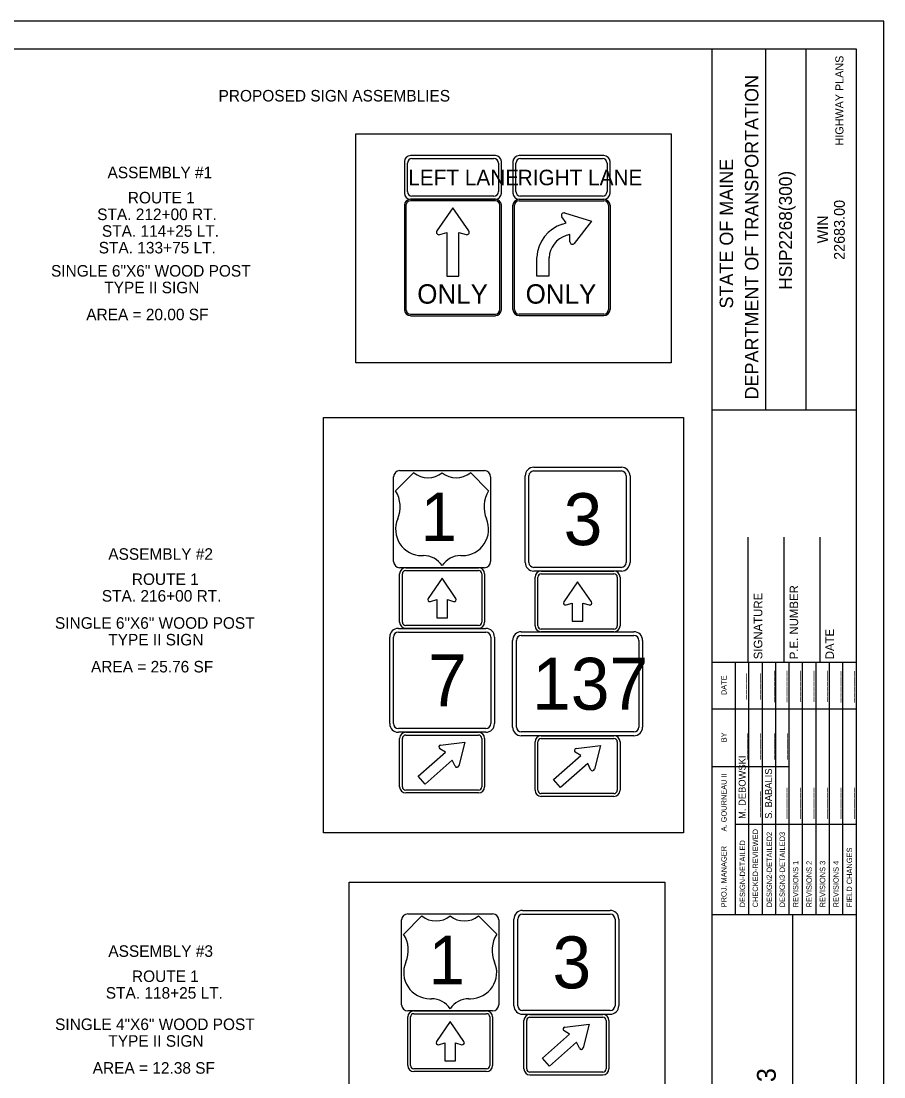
# Model space of a CAD drawing. Extents: x 29767 to 1670682, y 5748 to 339066.
# Drawn here: x 1670383.4 to 1670682.5, y 338699.8 to 339065.8 of the extents above; entities that cross this region are included whole.
import ezdxf

# ---------------------------------------------------------------- set-up
doc = ezdxf.new("R2010")
doc.units = 0
for name, color, linetype in [('D_Roadway_Pavement', 7, 'Continuous'), ('E_ROW_Line', 7, 'Continuous'), ('PDRAIN', 7, 'Continuous'), ('S_Curb_Type_5', 7, 'Continuous'), ('TEXT', 7, 'Continuous')]:
    doc.layers.add(name, color=color, linetype=linetype)

msp = doc.modelspace()

# ---------------------------------------------------------------- linework, layer by layer
at = {"layer": 'D_Roadway_Pavement'}
msp.add_lwpolyline([(1669832.5, 338515.81), (1670682.5, 338515.81), (1670682.5, 339065.81), (1669832.5, 339065.81)], close=True, dxfattribs=at)
at = {"layer": 'PDRAIN'}
for p, q in [((1670547.83, 339019.21), (1670518.39, 339019.21)), ((1670518.92, 339018.15), (1670547.31, 339018.15)), ((1670585.47, 339019.21), (1670556.04, 339019.21)), ((1670556.56, 339018.15), (1670584.95, 339018.15)), ((1670516.29, 339017.1), (1670516.29, 339006.17)), ((1670517.34, 339006.69), (1670517.34, 339016.58)), ((1670548.88, 339016.58), (1670548.88, 339006.69)), ((1670549.94, 339006.17), (1670549.94, 339017.1)), ((1670553.93, 339017.1), (1670553.93, 339006.17)), ((1670554.98, 339006.69), (1670554.98, 339016.58)), ((1670586.53, 339016.58), (1670586.53, 339006.69)), ((1670587.58, 339006.17), (1670587.58, 339017.1)), ((1670547.83, 339004.07), (1670518.39, 339004.07)), ((1670518.39, 339004.07), (1670547.83, 339004.07)), ((1670547.83, 339003.5), (1670518.39, 339003.5)), ((1670547.31, 339005.12), (1670518.92, 339005.12)), ((1670556.04, 339004.07), (1670585.47, 339004.07)), ((1670556.04, 339004.07), (1670585.47, 339004.07)), ((1670556.04, 339003.5), (1670585.47, 339003.5)), ((1670584.95, 339005.12), (1670556.56, 339005.12)), ((1670516.29, 339001.96), (1670516.29, 338965.8)), ((1670516.85, 339001.96), (1670516.85, 338965.8)), ((1670533.11, 339001.12), (1670527.58, 338993.08)), ((1670538.64, 338993.08), (1670533.11, 339001.12)), ((1670549.38, 338965.8), (1670549.38, 339001.96)), ((1670549.94, 338965.8), (1670549.94, 339001.96)), ((1670553.93, 338965.8), (1670553.93, 339001.96)), ((1670554.49, 338965.8), (1670554.49, 339001.96)), ((1670587.02, 339001.96), (1670587.02, 338965.8)), ((1670587.58, 339001.96), (1670587.58, 338965.8)), ((1670572.35, 338995.88), (1670570.85, 338998.01)), ((1670571.78, 338999.3), (1670581.13, 338996.5)), ((1670581.13, 338996.5), (1670575.17, 338988.77)), ((1670528.53, 338991.8), (1670531.01, 338992.58)), ((1670531.01, 338992.58), (1670531.01, 338977.43)), ((1670535.22, 338977.43), (1670535.22, 338992.58)), ((1670535.22, 338992.58), (1670537.7, 338991.8)), ((1670571.05, 338995.46), (1670572.35, 338995.88)), ((1670573.64, 338991.88), (1670572.34, 338991.46)), ((1670573.66, 338989.28), (1670573.64, 338991.88)), ((1670562.2, 338977.43), (1670562.2, 338983.88)), ((1670566.41, 338983.88), (1670566.41, 338977.43)), ((1670531.01, 338977.43), (1670535.22, 338977.43)), ((1670566.41, 338977.43), (1670562.2, 338977.43)), ((1670518.39, 338964.25), (1670547.83, 338964.25)), ((1670518.39, 338963.69), (1670547.83, 338963.69)), ((1670585.47, 338964.25), (1670556.04, 338964.25)), ((1670585.47, 338963.69), (1670556.04, 338963.69)), ((1670519.55, 338909.27), (1670513.25, 338902.96)), ((1670545.49, 338902.96), (1670539.18, 338909.27)), ((1670561.16, 338911.16), (1670591.5, 338911.16)), ((1670561.16, 338909.85), (1670591.5, 338909.85)), ((1670558.16, 338878.13), (1670558.16, 338908.16)), ((1670559.47, 338878.13), (1670559.47, 338908.16)), ((1670593.19, 338908.16), (1670593.19, 338878.13)), ((1670594.5, 338908.16), (1670594.5, 338878.13)), ((1670522.36, 338880.53), (1670522.9, 338880.53)), ((1670535.84, 338880.53), (1670536.38, 338880.53)), ((1670591.5, 338876.44), (1670561.16, 338876.44)), ((1670529.37, 338872.64), (1670524.58, 338865.68)), ((1670534.15, 338865.68), (1670529.37, 338872.64)), ((1670591.5, 338875.13), (1670561.16, 338875.13)), ((1670576.33, 338871.45), (1670571.55, 338864.48)), ((1670581.11, 338864.48), (1670576.33, 338871.45)), ((1670525.36, 338864.61), (1670527.53, 338865.26)), ((1670527.53, 338865.26), (1670527.53, 338858.97)), ((1670531.21, 338858.97), (1670531.21, 338865.26)), ((1670531.21, 338865.26), (1670533.37, 338864.61)), ((1670572.33, 338863.42), (1670574.49, 338864.06)), ((1670574.49, 338864.06), (1670574.49, 338857.78)), ((1670578.17, 338857.78), (1670578.17, 338864.06)), ((1670578.17, 338864.06), (1670580.34, 338863.42)), ((1670527.53, 338858.97), (1670531.21, 338858.97)), ((1670574.49, 338857.78), (1670578.17, 338857.78)), ((1670514.2, 338855.29), (1670544.53, 338855.29)), ((1670514.2, 338853.98), (1670544.53, 338853.98)), ((1670556.81, 338854.1), (1670595.85, 338854.1)), ((1670511.2, 338822.26), (1670511.2, 338852.29)), ((1670512.51, 338822.26), (1670512.51, 338852.29)), ((1670546.22, 338852.29), (1670546.22, 338822.26)), ((1670547.54, 338852.29), (1670547.54, 338822.26)), ((1670553.81, 338821.07), (1670553.81, 338851.1)), ((1670555.12, 338821.07), (1670555.12, 338851.1)), ((1670556.81, 338852.79), (1670595.85, 338852.79)), ((1670597.54, 338851.1), (1670597.54, 338821.07)), ((1670598.85, 338851.1), (1670598.85, 338821.07)), ((1670544.53, 338820.57), (1670514.2, 338820.57)), ((1670544.53, 338819.26), (1670514.2, 338819.26)), ((1670595.85, 338819.38), (1670556.81, 338819.38)), ((1670595.85, 338818.07), (1670556.81, 338818.07)), ((1670530.49, 338812.36), (1670528.57, 338813.56)), ((1670528.86, 338814.85), (1670537.25, 338815.84)), ((1670537.25, 338815.84), (1670535.17, 338807.66)), ((1670575.83, 338813.65), (1670584.22, 338814.65)), ((1670584.22, 338814.65), (1670582.14, 338806.46)), ((1670521.06, 338804.08), (1670530.49, 338812.36)), ((1670532.91, 338809.59), (1670523.48, 338801.32)), ((1670533.86, 338807.54), (1670532.91, 338809.59)), ((1670568.02, 338802.89), (1670577.45, 338811.16)), ((1670577.45, 338811.16), (1670575.54, 338812.36)), ((1670579.88, 338808.4), (1670570.45, 338800.12)), ((1670580.82, 338806.34), (1670579.88, 338808.4)), ((1670523.48, 338801.32), (1670521.06, 338804.08)), ((1670570.45, 338800.12), (1670568.02, 338802.89)), ((1670522.36, 338755.61), (1670516.05, 338749.3)), ((1670548.29, 338749.3), (1670541.98, 338755.61)), ((1670557.28, 338757.51), (1670587.62, 338757.51)), ((1670557.28, 338756.19), (1670587.62, 338756.19)), ((1670554.28, 338724.48), (1670554.28, 338754.5)), ((1670555.59, 338724.48), (1670555.59, 338754.5)), ((1670589.31, 338754.5), (1670589.31, 338724.48)), ((1670590.62, 338754.5), (1670590.62, 338724.48)), ((1670525.16, 338726.87), (1670525.7, 338726.87)), ((1670538.64, 338726.87), (1670539.18, 338726.87)), ((1670587.62, 338722.78), (1670557.28, 338722.78)), ((1670532.17, 338718.99), (1670527.39, 338712.02)), ((1670536.95, 338712.02), (1670532.17, 338718.99)), ((1670587.62, 338721.47), (1670557.28, 338721.47)), ((1670571.95, 338717.06), (1670580.34, 338718.06)), ((1670580.34, 338718.06), (1670578.26, 338709.87)), ((1670564.14, 338706.3), (1670573.57, 338714.57)), ((1670573.57, 338714.57), (1670571.66, 338715.77)), ((1670528.17, 338710.96), (1670530.33, 338711.6)), ((1670530.33, 338711.6), (1670530.33, 338705.32)), ((1670534.01, 338705.32), (1670534.01, 338711.6)), ((1670534.01, 338711.6), (1670536.18, 338710.96)), ((1670576, 338711.8), (1670566.57, 338703.53)), ((1670576.94, 338709.75), (1670576, 338711.8)), ((1670530.33, 338705.32), (1670534.01, 338705.32)), ((1670566.57, 338703.53), (1670564.14, 338706.3))]:
    msp.add_line(p, q, dxfattribs=at)
for points in [[(1670514.65, 338909.97), (1670544.09, 338909.97)], [(1670512.54, 338878.42), (1670512.54, 338907.86)], [(1670546.19, 338907.86), (1670546.19, 338878.42)], [(1670544.09, 338876.32), (1670514.65, 338876.32)], [(1670516.75, 338876.32), (1670541.98, 338876.32)], [(1670516.75, 338875.36), (1670541.98, 338875.36)], [(1670514.65, 338857.4), (1670514.65, 338874.22)], [(1670515.61, 338857.4), (1670515.61, 338874.22)], [(1670543.12, 338874.22), (1670543.12, 338857.4)], [(1670544.09, 338874.22), (1670544.09, 338857.4)], [(1670561.61, 338856.2), (1670561.61, 338873.02)], [(1670562.57, 338856.2), (1670562.57, 338873.02)], [(1670563.71, 338875.13), (1670588.95, 338875.13)], [(1670563.71, 338874.16), (1670588.95, 338874.16)], [(1670590.09, 338873.02), (1670590.09, 338856.2)], [(1670591.05, 338873.02), (1670591.05, 338856.2)], [(1670541.98, 338856.26), (1670516.75, 338856.26)], [(1670541.98, 338855.29), (1670516.75, 338855.29)], [(1670588.95, 338855.06), (1670563.71, 338855.06)], [(1670588.95, 338854.1), (1670563.71, 338854.1)], [(1670514.65, 338800.34), (1670514.65, 338817.16)], [(1670515.61, 338800.34), (1670515.61, 338817.16)], [(1670516.75, 338819.26), (1670541.98, 338819.26)], [(1670516.75, 338818.3), (1670541.98, 338818.3)], [(1670543.12, 338817.16), (1670543.12, 338800.34)], [(1670544.09, 338817.16), (1670544.09, 338800.34)], [(1670563.71, 338818.07), (1670588.95, 338818.07)], [(1670563.71, 338817.1), (1670588.95, 338817.1)], [(1670561.61, 338799.14), (1670561.61, 338815.96)], [(1670562.57, 338799.14), (1670562.57, 338815.96)], [(1670590.09, 338815.96), (1670590.09, 338799.14)], [(1670591.05, 338815.96), (1670591.05, 338799.14)], [(1670541.98, 338799.2), (1670516.75, 338799.2)], [(1670541.98, 338798.23), (1670516.75, 338798.23)], [(1670588.95, 338798), (1670563.71, 338798)], [(1670588.95, 338797.04), (1670563.71, 338797.04)], [(1670517.45, 338756.31), (1670546.89, 338756.31)], [(1670515.35, 338724.77), (1670515.35, 338754.21)], [(1670548.99, 338754.21), (1670548.99, 338724.77)], [(1670546.89, 338722.67), (1670517.45, 338722.67)], [(1670519.55, 338722.67), (1670544.79, 338722.67)], [(1670519.55, 338721.7), (1670544.79, 338721.7)], [(1670517.45, 338703.74), (1670517.45, 338720.56)], [(1670518.42, 338703.74), (1670518.42, 338720.56)], [(1670545.93, 338720.56), (1670545.93, 338703.74)], [(1670546.89, 338720.56), (1670546.89, 338703.74)], [(1670557.73, 338702.55), (1670557.73, 338719.37)], [(1670558.69, 338702.55), (1670558.69, 338719.37)], [(1670559.83, 338721.47), (1670585.07, 338721.47)], [(1670559.83, 338720.51), (1670585.07, 338720.51)], [(1670586.21, 338719.37), (1670586.21, 338702.55)], [(1670587.17, 338719.37), (1670587.17, 338702.55)], [(1670544.79, 338702.6), (1670519.55, 338702.6)], [(1670544.79, 338701.64), (1670519.55, 338701.64)], [(1670585.07, 338701.41), (1670559.83, 338701.41)], [(1670585.07, 338700.44), (1670559.83, 338700.44)]]:
    msp.add_lwpolyline(points, dxfattribs=at)
for centre, radius, start, end in [((1670518.39, 339017.1), 2.1, 90, 180), ((1670518.92, 339016.58), 1.58, 90, 180), ((1670547.31, 339016.58), 1.58, 0, 90), ((1670547.83, 339017.1), 2.1, 0, 90), ((1670556.04, 339017.1), 2.1, 90, 180), ((1670556.56, 339016.58), 1.58, 90, 180), ((1670584.95, 339016.58), 1.58, 0, 90), ((1670585.47, 339017.1), 2.1, 0, 90), ((1670518.39, 339006.17), 2.1, 180, 270), ((1670518.39, 339001.96), 2.1, 90, 180), ((1670518.39, 339001.96), 1.54, 90, 180), ((1670518.92, 339006.69), 1.58, 180, 270), ((1670547.31, 339006.69), 1.58, 270, 0), ((1670547.83, 339006.17), 2.1, 270, 0), ((1670547.83, 339001.96), 2.1, 0, 90), ((1670547.83, 339001.96), 1.54, 0, 90), ((1670556.04, 339006.17), 2.1, 180, 270), ((1670556.04, 339001.96), 2.1, 90, 180), ((1670556.04, 339001.96), 1.54, 90, 180), ((1670556.56, 339006.69), 1.58, 180, 270), ((1670584.95, 339006.69), 1.58, 270, 0), ((1670585.47, 339006.17), 2.1, 270, 0), ((1670585.47, 339001.96), 2.1, 0, 90), ((1670585.47, 339001.96), 1.54, 0, 90), ((1670571.54, 338998.49), 0.841, 73.3254, 215.2026), ((1670528.28, 338992.61), 0.841, 145.4854, 287.3626), ((1670537.95, 338992.61), 0.841, 252.6374, 34.5146), ((1670574.96, 338983.32), 12.76, 107.8394, 176.9831), ((1670574.96, 338983.32), 8.55, 107.8395, 176.9831), ((1670574.5, 338989.28), 0.841, 180.4774, 322.3546), ((1670518.39, 338965.8), 2.1, 180, 270), ((1670518.39, 338965.8), 1.54, 180, 270), ((1670547.83, 338965.8), 2.1, 270, 0), ((1670547.83, 338965.8), 1.54, 270, 0), ((1670556.04, 338965.8), 2.1, 180, 270), ((1670556.04, 338965.8), 1.54, 180, 270), ((1670585.47, 338965.8), 2.1, 270, 0), ((1670585.47, 338965.8), 1.54, 270, 0), ((1670514.65, 338907.86), 2.1, 90, 180), ((1670524.46, 338915.21), 7.71, 230.4788, 309.5212), ((1670534.27, 338915.21), 7.71, 230.4788, 309.5212), ((1670544.09, 338907.86), 2.1, 360, 90), ((1670561.16, 338908.16), 3, 90, 180), ((1670561.16, 338908.16), 1.69, 90, 180), ((1670591.5, 338908.16), 3, 0, 90), ((1670591.5, 338908.16), 1.69, 0, 90), ((1670504.33, 338897.39), 10.51, 336.7407, 31.9738), ((1670554.41, 338897.39), 10.51, 148.0262, 203.2593), ((1670522.36, 338889.64), 9.11, 156.7407, 270), ((1670536.38, 338889.64), 9.11, 270, 23.2593), ((1670522.9, 338872.82), 7.71, 33.0557, 90.0481), ((1670535.83, 338872.82), 7.71, 89.9519, 146.9443), ((1670514.65, 338878.42), 2.1, 180, 270), ((1670516.75, 338874.22), 2.1, 90, 180), ((1670516.75, 338874.22), 1.14, 90, 180), ((1670541.98, 338874.22), 2.1, 0, 90), ((1670541.98, 338874.22), 1.14, 0, 90), ((1670544.09, 338878.42), 2.1, 270, 360), ((1670561.16, 338878.13), 3, 180, 270), ((1670561.16, 338878.13), 1.69, 180, 270), ((1670591.5, 338878.13), 3, 270, 0), ((1670591.5, 338878.13), 1.69, 270, 0), ((1670563.71, 338873.02), 2.1, 90, 180), ((1670563.71, 338873.02), 1.14, 90, 180), ((1670588.95, 338873.02), 2.1, 0, 90), ((1670588.95, 338873.02), 1.14, 0, 90), ((1670525.16, 338865.28), 0.701, 145.5119, 286.6443), ((1670533.57, 338865.28), 0.701, 253.3557, 34.4881), ((1670572.12, 338864.09), 0.701, 145.5119, 286.6443), ((1670580.54, 338864.09), 0.701, 253.3557, 34.4881), ((1670516.75, 338857.4), 2.1, 180, 270), ((1670516.75, 338857.4), 1.14, 180, 270), ((1670541.98, 338857.4), 2.1, 270, 0), ((1670541.98, 338857.4), 1.14, 270, 0), ((1670514.2, 338852.29), 3, 90, 180), ((1670514.2, 338852.29), 1.69, 90, 180), ((1670544.53, 338852.29), 3, 0, 90), ((1670544.53, 338852.29), 1.69, 0, 90), ((1670556.81, 338851.1), 3, 90, 180), ((1670563.71, 338856.2), 2.1, 180, 270), ((1670563.71, 338856.2), 1.14, 180, 270), ((1670588.95, 338856.2), 2.1, 270, 0), ((1670588.95, 338856.2), 1.14, 270, 0), ((1670595.85, 338851.1), 3, 0, 90), ((1670556.81, 338851.1), 1.69, 90, 180), ((1670595.85, 338851.1), 1.69, 0, 90), ((1670514.2, 338822.26), 3, 180, 270), ((1670514.2, 338822.26), 1.69, 180, 270), ((1670544.53, 338822.26), 3, 270, 0), ((1670544.53, 338822.26), 1.69, 270, 0), ((1670556.81, 338821.07), 3, 180, 270), ((1670556.81, 338821.07), 1.69, 180, 270), ((1670595.85, 338821.07), 3, 270, 0), ((1670595.85, 338821.07), 1.69, 270, 0), ((1670516.75, 338817.16), 2.1, 90, 180), ((1670516.75, 338817.16), 1.14, 90, 180), ((1670541.98, 338817.16), 2.1, 0, 90), ((1670541.98, 338817.16), 1.14, 0, 90), ((1670563.71, 338815.96), 2.1, 90, 180), ((1670563.71, 338815.96), 1.14, 90, 180), ((1670588.95, 338815.96), 2.1, 0, 90), ((1670588.95, 338815.96), 1.14, 0, 90), ((1670528.95, 338814.15), 0.701, 96.7689, 237.9013), ((1670575.91, 338812.96), 0.701, 96.7689, 237.9013), ((1670534.49, 338807.83), 0.701, 204.6127, 345.7451), ((1670581.46, 338806.63), 0.701, 204.6127, 345.7451), ((1670516.75, 338800.34), 2.1, 180, 270), ((1670516.75, 338800.34), 1.14, 180, 270), ((1670541.98, 338800.34), 2.1, 270, 0), ((1670541.98, 338800.34), 1.14, 270, 0), ((1670563.71, 338799.14), 2.1, 180, 270), ((1670563.71, 338799.14), 1.14, 180, 270), ((1670588.95, 338799.14), 2.1, 270, 0), ((1670588.95, 338799.14), 1.14, 270, 0), ((1670517.45, 338754.21), 2.1, 90, 180), ((1670527.26, 338761.56), 7.71, 230.4788, 309.5212), ((1670537.08, 338761.56), 7.71, 230.4788, 309.5212), ((1670546.89, 338754.21), 2.1, 360, 90), ((1670557.28, 338754.5), 3, 90, 180), ((1670557.28, 338754.5), 1.69, 90, 180), ((1670587.62, 338754.5), 3, 0, 90), ((1670587.62, 338754.5), 1.69, 0, 90), ((1670507.13, 338743.73), 10.51, 336.7407, 31.9738), ((1670557.21, 338743.73), 10.51, 148.0262, 203.2593), ((1670525.16, 338735.98), 9.11, 156.7407, 270), ((1670539.18, 338735.98), 9.11, 270, 23.2593), ((1670525.71, 338719.16), 7.71, 33.0557, 90.0481), ((1670538.63, 338719.16), 7.71, 89.9519, 146.9443), ((1670517.45, 338724.77), 2.1, 180, 270), ((1670519.55, 338720.56), 2.1, 90, 180), ((1670519.55, 338720.56), 1.14, 90, 180), ((1670544.79, 338720.56), 2.1, 0, 90), ((1670544.79, 338720.56), 1.14, 0, 90), ((1670546.89, 338724.77), 2.1, 270, 360), ((1670557.28, 338724.48), 3, 180, 270), ((1670557.28, 338724.48), 1.69, 180, 270), ((1670587.62, 338724.48), 3, 270, 0), ((1670587.62, 338724.48), 1.69, 270, 0), ((1670559.83, 338719.37), 2.1, 90, 180), ((1670559.83, 338719.37), 1.14, 90, 180), ((1670585.07, 338719.37), 2.1, 0, 90), ((1670585.07, 338719.37), 1.14, 0, 90), ((1670572.03, 338716.36), 0.701, 96.7689, 237.9013), ((1670527.97, 338711.63), 0.701, 145.5119, 286.6443), ((1670536.38, 338711.63), 0.701, 253.3557, 34.4881), ((1670577.58, 338710.04), 0.701, 204.6127, 345.7451), ((1670519.55, 338703.74), 2.1, 180, 270), ((1670519.55, 338703.74), 1.14, 180, 270), ((1670544.79, 338703.74), 2.1, 270, 0), ((1670544.79, 338703.74), 1.14, 270, 0), ((1670559.83, 338702.55), 2.1, 180, 270), ((1670559.83, 338702.55), 1.14, 180, 270), ((1670585.07, 338702.55), 2.1, 270, 0), ((1670585.07, 338702.55), 1.14, 270, 0)]:
    msp.add_arc(centre, radius, start, end, dxfattribs=at)
at = {"layer": 'S_Curb_Type_5'}
for points in [[(1670499.44, 339026.77), (1670608.74, 339026.77), (1670608.74, 338947.38), (1670499.44, 338947.38)], [(1670488.3, 338928.39), (1670613.05, 338928.39), (1670613.05, 338784.39), (1670488.3, 338784.39)], [(1670497.21, 338767.33), (1670606.52, 338767.33), (1670606.52, 338687.94), (1670497.21, 338687.94)]]:
    msp.add_lwpolyline(points, close=True, dxfattribs=at)
at = {"layer": 'TEXT'}
for p, q in [((1670672.96, 339056.11), (1669872.96, 339056.11)), ((1670622.96, 338531.12), (1670622.96, 339056.12)), ((1670641.61, 338931.09), (1670641.61, 339056.09)), ((1670655.58, 338931.09), (1670655.58, 339056.09)), ((1670672.96, 338531.12), (1670672.96, 339056.12)), ((1670622.97, 338931.08), (1670672.96, 338931.08)), ((1670635.46, 338843.62), (1670635.46, 338886.86)), ((1670647.96, 338843.62), (1670647.96, 338886.86)), ((1670660.46, 338843.62), (1670660.46, 338886.86)), ((1670622.96, 338843.62), (1670672.96, 338843.62)), ((1670622.96, 338756.12), (1670672.96, 338756.12)), ((1670650.92, 338581.12), (1670650.92, 338756.12))]:
    msp.add_line(p, q, dxfattribs=at)
for points in [[(1670631.04, 338827.37), (1670631.04, 338843.62)], [(1670635.7, 338756.14), (1670635.7, 338843.62)], [(1670640.36, 338843.62), (1670640.36, 338756.14)], [(1670645.02, 338756.14), (1670645.02, 338843.62)], [(1670649.68, 338756.14), (1670649.68, 338843.62)], [(1670654.33, 338756.14), (1670654.33, 338843.62)], [(1670658.99, 338756.14), (1670658.99, 338843.62)], [(1670663.65, 338756.14), (1670663.65, 338843.62)], [(1670668.31, 338756.14), (1670668.31, 338843.62)], [(1670631.04, 338756.14), (1670631.04, 338840.09)], [(1670622.96, 338827.37), (1670672.96, 338827.37)], [(1670622.96, 338807.37), (1670631.04, 338807.37)], [(1670631.04, 338807.37), (1670649.67, 338807.37)], [(1670631.04, 338787.37), (1670672.96, 338787.37)]]:
    msp.add_lwpolyline(points, dxfattribs=at)

# ---------------------------------------------------------------- texts
at = {"layer": 'E_ROW_Line'}
for s, height, p in [('HIGHWAY PLANS', 2.795, (1670668.48, 339022.68)), ('US ROUTE 1 / STATE RTE 3', 6.5214, (1670645.02, 338587.99))]:
    msp.add_text(s, height=height, rotation=90, dxfattribs=at).set_placement(p)
at = {"layer": 'PDRAIN'}
for s, height, rotation, p in [('LEFT LANE', 5.383, 0, (1670517.64, 339008.91)), ('RIGHT LANE', 5.383, 0, (1670555.58, 339008.91)), ('ONLY', 6.728, 0, (1670520.75, 338967.86)), ('ONLY', 6.729, 0, (1670558.33, 338967.86)), ('1', 16.82, 360, (1670521.95, 338885.56)), ('3', 18.02, 0, (1670571.51, 338884.14)), ('7', 18.02, 0, (1670524.55, 338828.27)), ('137', 18.017, 0, (1670560.59, 338827.07)), ('1', 16.82, 360, (1670524.75, 338731.9)), ('3', 18.02, 0, (1670567.63, 338730.48))]:
    msp.add_text(s, height=height, rotation=rotation, dxfattribs=at).set_placement(p)
at = {"layer": 'S_Curb_Type_5'}
for s, p in [('PROPOSED SIGN ASSEMBLIES', (1670451.88, 339037.94)), ('ASSEMBLY #1', (1670413.4, 339011.33)), ('ROUTE 1', (1670420.44, 339002.61)), ('STA. 212+00 RT.', (1670409.82, 338996.83)), ('STA. 114+25 LT.', (1670411.45, 338991.05)), ('STA. 133+75 LT.', (1670410.35, 338985.27)), ('SINGLE 6"X6" WOOD POST', (1670393.81, 338977.23)), ('TYPE II SIGN', (1670412.26, 338971.46)), ('AREA = 20.00 SF', (1670406.03, 338962.1)), ('ASSEMBLY #2', (1670413.67, 338879.06)), ('ROUTE 1', (1670421.82, 338870.34)), ('STA. 216+00 RT.', (1670411.42, 338864.56)), ('SINGLE 6"X6" WOOD POST', (1670395.19, 338855.15)), ('TYPE II SIGN', (1670413.65, 338849.37)), ('AREA = 25.76 SF', (1670407.67, 338840.01)), ('ASSEMBLY #3', (1670413.68, 338741.41)), ('ROUTE 1', (1670421.86, 338732.69)), ('STA. 118+25 LT.', (1670412.8, 338726.91)), ('SINGLE 4"X6" WOOD POST', (1670395.23, 338716.03)), ('TYPE II SIGN', (1670413.69, 338710.25)), ('AREA = 12.38 SF', (1670408.27, 338700.9))]:
    msp.add_text(s, height=4, dxfattribs=at).set_placement(p)
at = {"layer": 'TEXT'}
for s, height, p in [('DEPARTMENT OF TRANSPORTATION', 4.6588, (1670639, 338934.64)), ('STATE OF MAINE', 4.6588, (1670630.24, 338966.17)), ('HSIP2268(300)', 4.4716, (1670650.63, 338972.67)), ('22683.00', 3.726, (1670668.94, 338983.04)), ('WIN', 3.726, (1670663.15, 338988.75)), ('P.E. NUMBER', 2.9528, (1670652.77, 338844.58)), ('SIGNATURE', 2.953, (1670640.37, 338844.58)), ('DATE', 2.953, (1670665.17, 338844.58)), ('_____', 2.423, (1670634.39, 338830.65)), ('_____', 2.423, (1670639.05, 338830.65)), ('______', 2.423, (1670643.89, 338829.75)), ('______', 2.423, (1670648.37, 338829.75)), ('______', 2.423, (1670653.03, 338829.76)), ('______', 2.423, (1670657.68, 338829.76)), ('______', 2.423, (1670662.34, 338829.76)), ('______', 2.423, (1670667, 338829.61)), ('______', 2.423, (1670671.66, 338829.61)), ('DATE', 1.857, (1670627.98, 338832.15)), ('BY', 1.857, (1670627.98, 338815.8)), ('_____', 2.423, (1670634.58, 338809.8)), ('_____', 2.423, (1670639.24, 338809.8)), ('_____', 2.423, (1670643.89, 338809.8)), ('_____', 2.423, (1670648.55, 338809.8)), ('M. DEBOWSKI', 2.4227, (1670634.58, 338789.24)), ('S. BABALIS', 2.423, (1670643.71, 338789.24)), ('A. GOURNEAU II', 1.8637, (1670627.98, 338784.9)), ('_____', 2.423, (1670639.24, 338789.8)), ('______', 2.423, (1670648.37, 338789.24)), ('______', 2.423, (1670653.03, 338789.24)), ('______', 2.423, (1670657.68, 338789.24)), ('______', 2.423, (1670662.34, 338789.24)), ('______', 2.423, (1670667, 338789.24)), ('______', 2.423, (1670671.66, 338789.24)), ('CHECKED-REVIEWED', 1.8637, (1670638.87, 338758.56)), ('DESIGN-DETAILED', 1.8637, (1670634.4, 338758.56)), ('DESIGN2-DETAILED2', 1.8637, (1670643.71, 338758.56)), ('DESIGN3-DETAILED3', 1.8637, (1670648.19, 338758.56)), ('PROJ. MANAGER', 1.8637, (1670627.98, 338758.56)), ('FIELD CHANGES', 1.8637, (1670671.48, 338758.56)), ('REVISIONS 1', 1.8637, (1670652.84, 338758.56)), ('REVISIONS 2', 1.8637, (1670657.5, 338758.56)), ('REVISIONS 3', 1.8637, (1670662.16, 338758.56)), ('REVISIONS 4', 1.8637, (1670666.82, 338758.56))]:
    msp.add_text(s, height=height, rotation=90, dxfattribs=at).set_placement(p)

doc.saveas('drawing.dxf')
